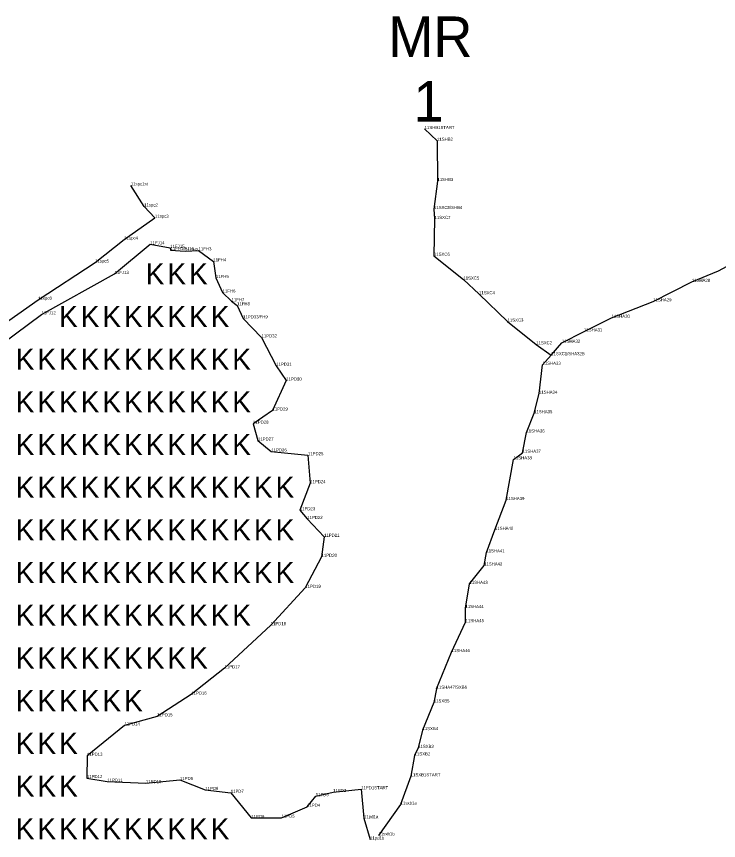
# Model space of a CAD drawing. Extents: x 2072529 to 2268812, y 436423 to 470008.
# Drawn here: x 2231934 to 2233068, y 447068 to 448400 of the extents above; entities that cross this region are included whole.
import ezdxf

# ---------------------------------------------------------------- set-up
doc = ezdxf.new("R2010")
doc.units = 0
for name, color, linetype in [('Old_Level_10', 7, 'Continuous'), ('Old_Level_20', 7, 'Continuous'), ('Old_Level_52', 7, 'Continuous'), ('Old_Level_55', 7, 'Continuous'), ('Old_Level_60', 7, 'Continuous'), ('Old_Level_62', 7, 'Continuous')]:
    doc.layers.add(name, color=color, linetype=linetype)

msp = doc.modelspace()

# ---------------------------------------------------------------- linework, layer by layer
at = {"layer": 'Old_Level_10'}
for points in [[(2232593.375, 448218.086), (2232613.487, 448199.105), (2232614.042, 448133.972), (2232608.529, 448088.718)], [(2230769.394, 447951.882), (2230820.468, 447870.14), (2230875.802, 447771.916), (2230917.643, 447710.638), (2230955.8, 447692.492), (2231037.496, 447706.907), (2231173.407, 447735.498), (2231315.304, 447761.122), (2231455.152, 447786.77), (2231613.245, 447790.272), (2231730.779, 447794.105), (2231802.313, 447822.04), (2231902.637, 447895.433), (2231968.706, 447942.06), (2232060.909, 448002.163), (2232107.899, 448039.336), (2232157.408, 448074.653), (2232140.017, 448092.714), (2232118.49, 448126.789)], [(2232608.529, 448088.718), (2232609.345, 448072.676), (2232608.346, 448013.14), (2232656.009, 447974.61), (2232681.327, 447950.905), (2232727.346, 447906.683), (2232773.615, 447869.889), (2232798.021, 447852.348)], [(2232612.696, 447313.071), (2232637.06, 447372.267), (2232659.727, 447420.704), (2232659.309, 447443.48), (2232665.83, 447482.549), (2232689.518, 447512.322), (2232693.189, 447533.526), (2232707.049, 447569.965), (2232725.142, 447618.207), (2232737.08, 447683.944), (2232751.704, 447694.613), (2232757.834, 447727.378), (2232770.302, 447758.566), (2232778.285, 447790.189), (2232783.806, 447836.842), (2232798.021, 447852.348), (2232815.241, 447872.574), (2232850.997, 447890.766), (2232895.505, 447912.838), (2232962.765, 447939.313), (2233025.331, 447970.873), (2233068.133, 447988.752), (2233109.111, 448010.902)], [(2232612.696, 447313.071), (2232608.184, 447290.969), (2232589.797, 447246.11), (2232582.904, 447217.415), (2232577.282, 447205.229), (2232570.904, 447171.565), (2232554.62, 447125.797), (2232518.839, 447075.824)]]:
    msp.add_lwpolyline(points, dxfattribs=at)
at = {"layer": 'Old_Level_20'}
for p, q in [((2232593.375, 448218.086), (2232593.375, 448218.086)), ((2232613.487, 448199.105), (2232613.487, 448199.105)), ((2232614.042, 448133.972), (2232614.042, 448133.972)), ((2232118.49, 448126.789), (2232118.49, 448126.789)), ((2232140.017, 448092.714), (2232140.017, 448092.714)), ((2232608.529, 448088.718), (2232608.529, 448088.718)), ((2232157.408, 448074.653), (2232157.408, 448074.653)), ((2232609.345, 448072.676), (2232609.345, 448072.676)), ((2232107.899, 448039.336), (2232107.899, 448039.336)), ((2232150.085, 448031.67), (2232150.085, 448031.67)), ((2232182.338, 448025.891), (2232182.338, 448025.891)), ((2232182.659, 448022.257), (2232182.659, 448022.257)), ((2232206.493, 448020.548), (2232206.493, 448020.548)), ((2232228.136, 448021.901), (2232228.136, 448021.901)), ((2232608.346, 448013.14), (2232608.346, 448013.14)), ((2232060.909, 448002.163), (2232060.909, 448002.163)), ((2232252.01, 448003.981), (2232252.01, 448003.981)), ((2233068.133, 447988.752), (2233068.133, 447988.752)), ((2232092.405, 447983.739), (2232092.405, 447983.739)), ((2232256.208, 447977.236), (2232256.208, 447977.236)), ((2232656.009, 447974.61), (2232656.009, 447974.61)), ((2233025.331, 447970.873), (2233025.331, 447970.873)), ((2232266.914, 447953.653), (2232266.914, 447953.653)), ((2232681.327, 447950.905), (2232681.327, 447950.905)), ((2231968.706, 447942.06), (2231968.706, 447942.06)), ((2232281.365, 447939.706), (2232281.365, 447939.706)), ((2232290.288, 447932.906), (2232290.288, 447932.906)), ((2232962.765, 447939.313), (2232962.765, 447939.313)), ((2231974.226, 447918.42), (2231974.226, 447918.42)), ((2232299.999, 447911.823), (2232299.999, 447911.823)), ((2232727.346, 447906.683), (2232727.346, 447906.683)), ((2232895.505, 447912.838), (2232895.505, 447912.838)), ((2232329.726, 447881.061), (2232329.726, 447881.061)), ((2232850.997, 447890.766), (2232850.997, 447890.766)), ((2232773.615, 447869.889), (2232773.615, 447869.889)), ((2232815.241, 447872.574), (2232815.241, 447872.574)), ((2232798.021, 447852.348), (2232798.021, 447852.348)), ((2232353.53, 447835.261), (2232353.53, 447835.261)), ((2232783.806, 447836.842), (2232783.806, 447836.842)), ((2232369.784, 447811.41), (2232369.784, 447811.41)), ((2232778.285, 447790.189), (2232778.285, 447790.189)), ((2232347.393, 447762.858), (2232347.393, 447762.858)), ((2232770.302, 447758.566), (2232770.302, 447758.566)), ((2232316.102, 447741.64), (2232316.102, 447741.64)), ((2232757.834, 447727.378), (2232757.834, 447727.378)), ((2232324.101, 447714.31), (2232324.101, 447714.31)), ((2232345.63, 447696.625), (2232345.63, 447696.625)), ((2232751.704, 447694.613), (2232751.704, 447694.613)), ((2232404.868, 447690.624), (2232404.868, 447690.624)), ((2232737.08, 447683.944), (2232737.08, 447683.944)), ((2232408.439, 447645.378), (2232408.439, 447645.378)), ((2232725.142, 447618.207), (2232725.142, 447618.207)), ((2232391.669, 447601.689), (2232391.669, 447601.689)), ((2232403.615, 447587.573), (2232403.615, 447587.573)), ((2232430.876, 447558.677), (2232430.876, 447558.677)), ((2232707.049, 447569.965), (2232707.049, 447569.965)), ((2232693.189, 447533.526), (2232693.189, 447533.526)), ((2232426.828, 447526.312), (2232426.828, 447526.312)), ((2232689.518, 447512.322), (2232689.518, 447512.322)), ((2232665.83, 447482.549), (2232665.83, 447482.549)), ((2232400.609, 447476.118), (2232400.609, 447476.118)), ((2232659.309, 447443.48), (2232659.309, 447443.48)), ((2232344.648, 447415.78), (2232344.648, 447415.78)), ((2232659.727, 447420.704), (2232659.727, 447420.704)), ((2232637.06, 447372.267), (2232637.06, 447372.267)), ((2232270.033, 447346.104), (2232270.033, 447346.104)), ((2232612.696, 447313.071), (2232612.696, 447313.071)), ((2232216.194, 447303.605), (2232216.194, 447303.605)), ((2232608.184, 447290.969), (2232608.184, 447290.969)), ((2232161.019, 447268.416), (2232161.019, 447268.416)), ((2232108.263, 447253.591), (2232108.263, 447253.591)), ((2232589.797, 447246.11), (2232589.797, 447246.11)), ((2232582.904, 447217.415), (2232582.904, 447217.415)), ((2232047.79, 447204.637), (2232047.79, 447204.637)), ((2232577.282, 447205.229), (2232577.282, 447205.229)), ((2232047.466, 447168.526), (2232047.466, 447168.526)), ((2232080.48, 447162.849), (2232080.48, 447162.849)), ((2232143.033, 447160.382), (2232143.033, 447160.382)), ((2232197.893, 447165.558), (2232197.893, 447165.558)), ((2232570.904, 447171.565), (2232570.904, 447171.565)), ((2232238.934, 447149.466), (2232238.934, 447149.466)), ((2232445.47, 447146.094), (2232445.47, 447146.094)), ((2232490.753, 447150.56), (2232490.753, 447150.56)), ((2232280.088, 447144.732), (2232280.088, 447144.732)), ((2232417.455, 447139.345), (2232417.455, 447139.345)), ((2232403.53, 447122.196), (2232403.53, 447122.196)), ((2232554.62, 447125.797), (2232554.62, 447125.797)), ((2232313.331, 447104.144), (2232313.331, 447104.144)), ((2232362.238, 447104.583), (2232362.238, 447104.583)), ((2232495.376, 447103.782), (2232495.376, 447103.782)), ((2232505.173, 447069.177), (2232505.173, 447069.177)), ((2232518.839, 447075.824), (2232518.839, 447075.824))]:
    msp.add_line(p, q, dxfattribs=at)
at = {"layer": 'Old_Level_52'}
for points in [[(2231807.646, 447794.925), (2231974.226, 447918.42), (2232092.405, 447983.739), (2232150.085, 448031.67), (2232182.338, 448025.891), (2232182.659, 448022.257), (2232206.493, 448020.548), (2232228.136, 448021.901), (2232252.01, 448003.981), (2232256.208, 447977.236), (2232266.914, 447953.653), (2232281.365, 447939.706), (2232290.288, 447932.906), (2232299.999, 447911.823), (2232329.726, 447881.061), (2232353.53, 447835.261), (2232369.784, 447811.41), (2232347.393, 447762.858), (2232316.102, 447741.64), (2232324.101, 447714.31), (2232345.63, 447696.625), (2232404.868, 447690.624), (2232408.439, 447645.378), (2232391.669, 447601.689), (2232403.615, 447587.573), (2232430.876, 447558.677), (2232426.828, 447526.312), (2232400.609, 447476.118), (2232344.648, 447415.78), (2232270.033, 447346.104), (2232216.194, 447303.605), (2232161.019, 447268.416), (2232108.263, 447253.591), (2232047.79, 447204.637), (2232047.466, 447168.526), (2232080.48, 447162.849), (2232143.033, 447160.382), (2232197.893, 447165.558), (2232238.934, 447149.466), (2232280.088, 447144.732), (2232313.331, 447104.144), (2232362.238, 447104.583), (2232403.53, 447122.196), (2232417.455, 447139.345), (2232445.47, 447146.094), (2232490.753, 447150.56)], [(2232490.753, 447150.56), (2232495.376, 447103.782), (2232505.173, 447069.177)]]:
    msp.add_lwpolyline(points, dxfattribs=at)

# ---------------------------------------------------------------- texts
at = {"layer": 'Old_Level_55'}
for p in [(2232142.479, 447966.791), (2232177.479, 447966.791), (2232212.479, 447966.791), (2232002.479, 447897.791), (2232037.479, 447897.791), (2232072.479, 447897.791), (2232107.479, 447897.791), (2232142.479, 447897.791), (2232177.479, 447897.791), (2232212.479, 447897.791), (2232247.479, 447897.791), (2231932.479, 447828.791), (2231967.479, 447828.791), (2232002.479, 447828.791), (2232037.479, 447828.791), (2232072.479, 447828.791), (2232107.479, 447828.791), (2232142.479, 447828.791), (2232177.479, 447828.791), (2232212.479, 447828.791), (2232247.479, 447828.791), (2232282.479, 447828.791), (2231932.479, 447759.791), (2231967.479, 447759.791), (2232002.479, 447759.791), (2232037.479, 447759.791), (2232072.479, 447759.791), (2232107.479, 447759.791), (2232142.479, 447759.791), (2232177.479, 447759.791), (2232212.479, 447759.791), (2232247.479, 447759.791), (2232282.479, 447759.791), (2231932.479, 447690.791), (2231967.479, 447690.791), (2232002.479, 447690.791), (2232037.479, 447690.791), (2232072.479, 447690.791), (2232107.479, 447690.791), (2232142.479, 447690.791), (2232177.479, 447690.791), (2232212.479, 447690.791), (2232247.479, 447690.791), (2232282.479, 447690.791), (2231932.479, 447621.791), (2231967.479, 447621.791), (2232002.479, 447621.791), (2232037.479, 447621.791), (2232072.479, 447621.791), (2232107.479, 447621.791), (2232142.479, 447621.791), (2232177.479, 447621.791), (2232212.479, 447621.791), (2232247.479, 447621.791), (2232282.479, 447621.791), (2232317.479, 447621.791), (2232352.479, 447621.791), (2231932.479, 447552.791), (2231967.479, 447552.791), (2232002.479, 447552.791), (2232037.479, 447552.791), (2232072.479, 447552.791), (2232107.479, 447552.791), (2232142.479, 447552.791), (2232177.479, 447552.791), (2232212.479, 447552.791), (2232247.479, 447552.791), (2232282.479, 447552.791), (2232317.479, 447552.791), (2232352.479, 447552.791), (2231932.479, 447483.791), (2231967.479, 447483.791), (2232002.479, 447483.791), (2232037.479, 447483.791), (2232072.479, 447483.791), (2232107.479, 447483.791), (2232142.479, 447483.791), (2232177.479, 447483.791), (2232212.479, 447483.791), (2232247.479, 447483.791), (2232282.479, 447483.791), (2232317.479, 447483.791), (2232352.479, 447483.791), (2231932.479, 447414.791), (2231967.479, 447414.791), (2232002.479, 447414.791), (2232037.479, 447414.791), (2232072.479, 447414.791), (2232107.479, 447414.791), (2232142.479, 447414.791), (2232177.479, 447414.791), (2232212.479, 447414.791), (2232247.479, 447414.791), (2232282.479, 447414.791), (2231932.479, 447345.791), (2231967.479, 447345.791), (2232002.479, 447345.791), (2232037.479, 447345.791), (2232072.479, 447345.791), (2232107.479, 447345.791), (2232142.479, 447345.791), (2232177.479, 447345.791), (2232212.479, 447345.791), (2231932.479, 447276.791), (2231967.479, 447276.791), (2232002.479, 447276.791), (2232037.479, 447276.791), (2232072.479, 447276.791), (2232107.479, 447276.791), (2231932.479, 447207.791), (2231967.479, 447207.791), (2232002.479, 447207.791), (2231932.479, 447138.791), (2231967.479, 447138.791), (2232002.479, 447138.791), (2231932.479, 447069.791), (2231967.479, 447069.791), (2232002.479, 447069.791), (2232037.479, 447069.791), (2232072.479, 447069.791), (2232107.479, 447069.791), (2232142.479, 447069.791), (2232177.479, 447069.791), (2232212.479, 447069.791), (2232247.479, 447069.791)]:
    msp.add_text('K', height=34, dxfattribs=at).set_placement(p)
at = {"layer": 'Old_Level_60'}
for s, p in [('11SHB1START', (2232593.375, 448218.086)), ('11SHB2', (2232613.487, 448199.105)), ('11spc1st', (2232118.49, 448126.789)), ('11SHB3', (2232614.042, 448133.972)), ('11spc2', (2232140.017, 448092.714)), ('11SXC8/SHB4', (2232608.529, 448088.718)), ('11spc3', (2232157.408, 448074.653)), ('11SXC7', (2232609.345, 448072.676)), ('11spc4', (2232107.899, 448039.336)), ('11FJ14', (2232150.085, 448031.67)), ('11FJ15', (2232182.338, 448025.891)), ('11FH1/FJ16', (2232182.659, 448022.257)), ('11FH2', (2232206.493, 448020.548)), ('11FH3', (2232228.136, 448021.901)), ('11SXC6', (2232608.346, 448013.14)), ('11spc5', (2232060.909, 448002.163)), ('11FH4', (2232252.01, 448003.981)), ('11FJ13', (2232092.405, 447983.739)), ('11FH5', (2232256.208, 447977.236)), ('11SXC5', (2232656.009, 447974.61)), ('11SHA28', (2233025.331, 447970.873)), ('11FH6', (2232266.914, 447953.653)), ('11xpc6', (2231968.706, 447942.06)), ('11FH7', (2232281.365, 447939.706)), ('11SXC4', (2232681.327, 447950.905)), ('11FH8', (2232290.288, 447932.906)), ('11SHA29', (2232962.765, 447939.313)), ('11FJ12', (2231974.226, 447918.42)), ('11SHA30', (2232895.505, 447912.838)), ('11PD33/FH9', (2232299.999, 447911.823)), ('11SXC3', (2232727.346, 447906.683)), ('11SHA31', (2232850.997, 447890.766)), ('11PD32', (2232329.726, 447881.061)), ('11SXC2', (2232773.615, 447869.889)), ('11SHA32', (2232815.241, 447872.574)), ('11SXC1/SHA32B', (2232798.021, 447852.348)), ('11PD31', (2232353.53, 447835.261)), ('11SHA33', (2232783.806, 447836.842)), ('11PD30', (2232369.784, 447811.41)), ('11SHA34', (2232778.285, 447790.189)), ('11PD29', (2232347.393, 447762.858)), ('11SHA35', (2232770.302, 447758.566)), ('11PD28', (2232316.102, 447741.64)), ('11SHA36', (2232757.834, 447727.378)), ('11PD27', (2232324.101, 447714.31)), ('11PD26', (2232345.63, 447696.625)), ('11PD25', (2232404.868, 447690.624)), ('11SHA37', (2232751.704, 447694.613)), ('11SHA38', (2232737.08, 447683.944)), ('11PD24', (2232408.439, 447645.378)), ('11SHA39', (2232725.142, 447618.207)), ('11PD23', (2232391.669, 447601.689)), ('11PD22', (2232403.615, 447587.573)), ('11SHA40', (2232707.049, 447569.965)), ('11PD21', (2232430.876, 447558.677)), ('11PD20', (2232426.828, 447526.312)), ('11SHA41', (2232693.189, 447533.526)), ('11SHA42', (2232689.518, 447512.322)), ('11PD19', (2232400.609, 447476.118)), ('11SHA43', (2232665.83, 447482.549)), ('11SHA44', (2232659.309, 447443.48)), ('11SHA45', (2232659.727, 447420.704)), ('11PD18', (2232344.648, 447415.78)), ('11SHA46', (2232637.06, 447372.267)), ('11PD17', (2232270.033, 447346.104)), ('11SHA47/SXB6', (2232612.696, 447313.071)), ('11PD16', (2232216.194, 447303.605)), ('11SXB5', (2232608.184, 447290.969)), ('11PD15', (2232161.019, 447268.416)), ('11PD14', (2232108.263, 447253.591)), ('11SXB4', (2232589.797, 447246.11)), ('11SXB3', (2232582.904, 447217.415)), ('11PD13', (2232047.79, 447204.637)), ('11SXB2', (2232577.282, 447205.229)), ('11PD12', (2232047.466, 447168.526)), ('11SXB1START', (2232570.904, 447171.565)), ('11PD11', (2232080.48, 447162.849)), ('11PD10', (2232143.033, 447160.382)), ('11PD9', (2232197.893, 447165.558)), ('11PD8', (2232238.934, 447149.466)), ('11PD7', (2232280.088, 447144.732)), ('11PD2', (2232445.47, 447146.094)), ('11PD1START', (2232490.753, 447150.56)), ('11PD3', (2232417.455, 447139.345)), ('11PD4', (2232403.53, 447122.196)), ('11sxb1a', (2232554.62, 447125.797)), ('11PD6', (2232313.331, 447104.144)), ('11PD5', (2232362.238, 447104.583)), ('11pd1a', (2232495.376, 447103.782)), ('11sxb1b', (2232518.839, 447075.824)), ('11pd1b', (2232505.173, 447069.177))]:
    msp.add_text(s, height=5, dxfattribs=at).set_placement(p)
at = {"layer": 'Old_Level_62'}
for s, p in [('MR', (2232534.779, 448334.664)), ('1', (2232575.513, 448230.12))]:
    msp.add_text(s, height=65.34, dxfattribs=at).set_placement(p)

doc.saveas('drawing.dxf')
